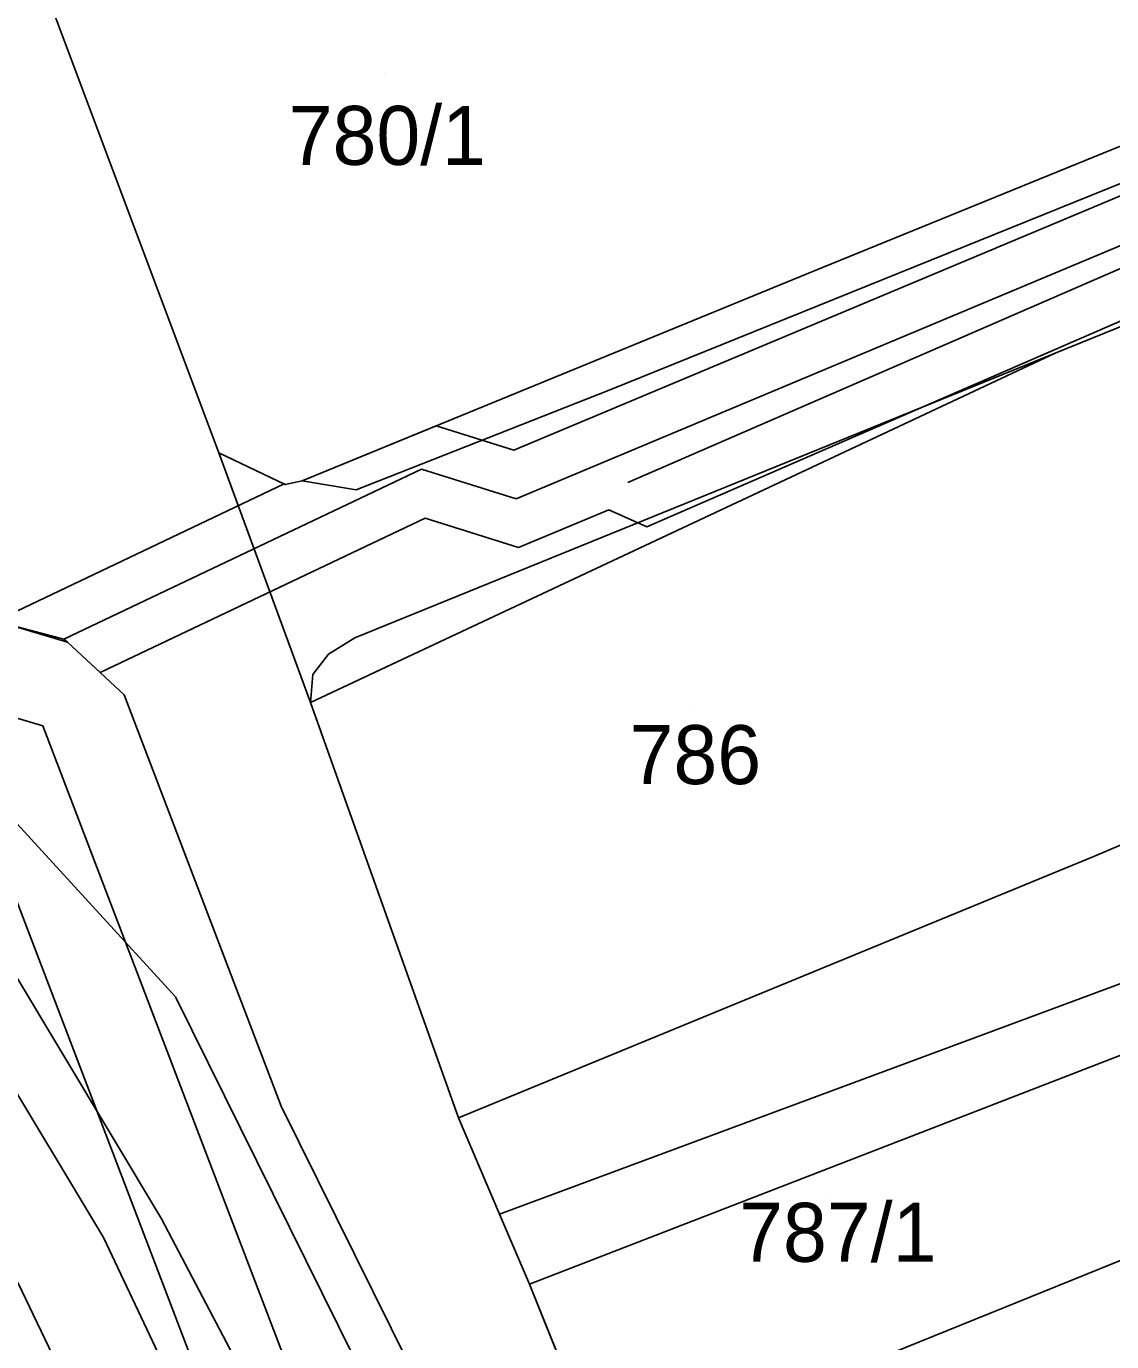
# Model space of a CAD drawing. Extents: x -263423 to -261326, y -1240067 to -1237864.
# Drawn here: x -262860.21 to -262823.4, y -1239293 to -1239248.39 of the extents above; entities that cross this region are included whole.
import ezdxf

# ---------------------------------------------------------------- set-up
doc = ezdxf.new("R2010")
doc.units = 0
for name, color, linetype in [('body_kn', 7, 'Continuous'), ('kladpar_druhypozemkov', 7, 'Continuous'), ('kladpar_hranice', 7, 'Continuous'), ('kladpar_parcelnecisla', 7, 'Continuous'), ('kladpar_plochy', 7, 'Continuous'), ('tarchy_linie', 7, 'Continuous'), ('zappar_hrandruhpozemk', 7, 'Continuous')]:
    doc.layers.add(name, color=color, linetype=linetype)

msp = doc.modelspace()

# ---------------------------------------------------------------- linework, layer by layer
at = {"layer": 'body_kn'}
for p, q in [((-262833.51, -1239256.69), (-262833.51, -1239256.69)), ((-262825.32, -1239259.48), (-262825.32, -1239259.48)), ((-262840.45, -1239260.73), (-262840.45, -1239260.73)), ((-262846.31, -1239261.94), (-262846.31, -1239261.94)), ((-262853.69, -1239262.86), (-262853.69, -1239262.86)), ((-262843.68, -1239262.77), (-262843.68, -1239262.77)), ((-262846.81, -1239263.41), (-262846.81, -1239263.41)), ((-262851.47, -1239263.91), (-262851.47, -1239263.91)), ((-262851.43, -1239263.93), (-262851.43, -1239263.93)), ((-262850.86, -1239263.81), (-262850.86, -1239263.81)), ((-262839.81, -1239263.86), (-262839.81, -1239263.86)), ((-262849.03, -1239264.11), (-262849.03, -1239264.11)), ((-262843.6, -1239264.42), (-262843.6, -1239264.42)), ((-262840.46, -1239264.79), (-262840.46, -1239264.79)), ((-262846.69, -1239265.07), (-262846.69, -1239265.07)), ((-262839.17, -1239265.37), (-262839.17, -1239265.37)), ((-262843.52, -1239266.07), (-262843.52, -1239266.07)), ((-262858.94, -1239269.17), (-262858.94, -1239269.17)), ((-262858.94, -1239269.17), (-262858.94, -1239269.17)), ((-262858.82, -1239269.28), (-262858.82, -1239269.28)), ((-262849.07, -1239269.13), (-262849.07, -1239269.13)), ((-262849.97, -1239269.68), (-262849.97, -1239269.68)), ((-262857.71, -1239270.3), (-262857.71, -1239270.3)), ((-262850.5, -1239270.37), (-262850.5, -1239270.37)), ((-262856.89, -1239271.06), (-262856.89, -1239271.06)), ((-262850.58, -1239271.32), (-262850.58, -1239271.32)), ((-262850.58, -1239271.32), (-262850.58, -1239271.32)), ((-262859.65, -1239272.11), (-262859.65, -1239272.11)), ((-262823.98, -1239276.53), (-262823.98, -1239276.53)), ((-262823.98, -1239276.53), (-262823.98, -1239276.53)), ((-262855.16, -1239281.3), (-262855.16, -1239281.3)), ((-262851.57, -1239285.01), (-262851.57, -1239285.01)), ((-262845.56, -1239285.41), (-262845.56, -1239285.41)), ((-262855.63, -1239288.83), (-262855.63, -1239288.83)), ((-262844.17, -1239288.68), (-262844.17, -1239288.68)), ((-262857.6, -1239289.47), (-262857.6, -1239289.47)), ((-262843.15, -1239291.05), (-262843.15, -1239291.05)), ((-262843.15, -1239291.05), (-262843.15, -1239291.05))]:
    msp.add_line(p, q, dxfattribs=at)
at = {"layer": 'kladpar_druhypozemkov'}
for p, q in [((-262848.07, -1239249.99), (-262848.07, -1239249.99)), ((-262837.67, -1239271.49), (-262837.67, -1239271.49)), ((-262833.07, -1239288.09), (-262833.07, -1239288.09))]:
    msp.add_line(p, q, dxfattribs=at)
at = {"layer": 'kladpar_hranice'}
for points in [[(-262876.94, -1239194.62), (-262873.93, -1239204.53), (-262869.83, -1239217.58), (-262867.69, -1239224.11), (-262867.04, -1239226.16), (-262865.44, -1239231.28), (-262860.88, -1239243.51), (-262859.93, -1239246.2), (-262853.69, -1239262.86), (-262850.58, -1239271.32), (-262845.56, -1239285.41), (-262844.17, -1239288.68), (-262843.15, -1239291.05), (-262840.62, -1239297.33)], [(-262801.24, -1239243.54), (-262833.51, -1239256.69), (-262850.86, -1239263.81), (-262851.43, -1239263.93), (-262853.69, -1239262.86), (-262859.93, -1239246.2), (-262860.88, -1239243.51), (-262865.44, -1239231.28), (-262838.39, -1239221.89), (-262811.78, -1239209.44)], [(-262801.24, -1239243.54), (-262781.39, -1239235.39), (-262754.82, -1239224.92), (-262754.34, -1239223.21), (-262753.82, -1239222.65), (-262752.93, -1239225.34), (-262751.64, -1239230.32), (-262766.74, -1239235.9), (-262771.22, -1239237.71), (-262775.96, -1239239.64), (-262785.18, -1239243.38), (-262805.66, -1239251.51), (-262825.32, -1239259.48), (-262850.58, -1239271.32), (-262853.69, -1239262.86), (-262851.43, -1239263.93), (-262850.86, -1239263.81), (-262833.51, -1239256.69), (-262801.24, -1239243.54)], [(-262805.66, -1239251.51), (-262803.75, -1239256.77), (-262803.39, -1239257.92), (-262801.95, -1239261.7), (-262800.22, -1239266.44), (-262823.98, -1239276.53), (-262845.56, -1239285.41), (-262850.58, -1239271.32), (-262825.32, -1239259.48), (-262805.66, -1239251.51)], [(-262823.98, -1239276.53), (-262800.22, -1239266.44), (-262794.84, -1239264.08), (-262792.97, -1239268.69), (-262796.94, -1239270.32), (-262822.48, -1239280.63), (-262821.58, -1239282.69), (-262819.17, -1239288.65), (-262840.62, -1239297.33), (-262843.15, -1239291.05), (-262844.17, -1239288.68), (-262845.56, -1239285.41), (-262823.98, -1239276.53)], [(-262793.62, -1239277.89), (-262788.75, -1239275.84), (-262785.54, -1239274.49), (-262783.04, -1239280.5), (-262787.13, -1239282.2), (-262786.51, -1239283.89), (-262785.37, -1239286.59), (-262785.19, -1239287.1), (-262787.22, -1239287.18), (-262790.65, -1239287.43), (-262790.83, -1239286.91), (-262793.88, -1239287.04), (-262799.31, -1239288.83), (-262813.6, -1239295.06), (-262837.24, -1239305.09), (-262840.62, -1239297.33), (-262819.17, -1239288.65), (-262793.62, -1239277.89)]]:
    msp.add_lwpolyline(points, dxfattribs=at)
at = {"layer": 'kladpar_plochy'}
for p, q in [((-262859.93, -1239246.2), (-262853.69, -1239262.86)), ((-262853.69, -1239262.86), (-262850.58, -1239271.32)), ((-262850.58, -1239271.32), (-262845.56, -1239285.41)), ((-262845.56, -1239285.41), (-262844.17, -1239288.68)), ((-262844.17, -1239288.68), (-262843.15, -1239291.05)), ((-262843.15, -1239291.05), (-262840.62, -1239297.33))]:
    msp.add_line(p, q, dxfattribs=at)
msp.add_lwpolyline([(-262801.24, -1239243.54), (-262833.51, -1239256.69), (-262850.86, -1239263.81), (-262851.43, -1239263.93), (-262853.69, -1239262.86), (-262859.93, -1239246.2), (-262860.88, -1239243.51), (-262865.44, -1239231.28), (-262838.39, -1239221.89), (-262811.78, -1239209.44)], dxfattribs=at)
for points in [[(-262801.24, -1239243.54), (-262781.39, -1239235.39), (-262754.82, -1239224.92), (-262754.34, -1239223.21), (-262753.82, -1239222.65), (-262752.93, -1239225.34), (-262751.64, -1239230.32), (-262766.74, -1239235.9), (-262771.22, -1239237.71), (-262775.96, -1239239.64), (-262785.18, -1239243.38), (-262805.66, -1239251.51), (-262825.32, -1239259.48), (-262850.58, -1239271.32), (-262853.69, -1239262.86), (-262851.43, -1239263.93), (-262850.86, -1239263.81), (-262833.51, -1239256.69)], [(-262805.66, -1239251.51), (-262803.75, -1239256.77), (-262803.39, -1239257.92), (-262801.95, -1239261.7), (-262800.22, -1239266.44), (-262823.98, -1239276.53), (-262845.56, -1239285.41), (-262850.58, -1239271.32), (-262825.32, -1239259.48)], [(-262823.98, -1239276.53), (-262800.22, -1239266.44), (-262794.84, -1239264.08), (-262792.97, -1239268.69), (-262796.94, -1239270.32), (-262822.48, -1239280.63), (-262821.58, -1239282.69), (-262819.17, -1239288.65), (-262840.62, -1239297.33), (-262843.15, -1239291.05), (-262844.17, -1239288.68), (-262845.56, -1239285.41)], [(-262793.62, -1239277.89), (-262788.75, -1239275.84), (-262785.54, -1239274.49), (-262783.04, -1239280.5), (-262787.13, -1239282.2), (-262786.51, -1239283.89), (-262785.37, -1239286.59), (-262785.19, -1239287.1), (-262787.22, -1239287.18), (-262790.65, -1239287.43), (-262790.83, -1239286.91), (-262793.88, -1239287.04), (-262799.31, -1239288.83), (-262813.6, -1239295.06), (-262837.24, -1239305.09), (-262840.62, -1239297.33), (-262819.17, -1239288.65)]]:
    msp.add_lwpolyline(points, close=True, dxfattribs=at)
at = {"layer": 'tarchy_linie'}
for points in [[(-262919.47, -1239083.19), (-262910.4, -1239113.29), (-262903.08, -1239136.85), (-262892.92, -1239170.2), (-262878.03, -1239218.5), (-262872.8, -1239236.18), (-262865.97, -1239259.6), (-262862.37, -1239270.8), (-262860.78, -1239275.15), (-262855.16, -1239281.3), (-262847.42, -1239296.93), (-262841.21, -1239314.37), (-262837.3, -1239325.72), (-262833.82, -1239334.62), (-262823.57, -1239363.35), (-262812.24, -1239393.87)], [(-262858.94, -1239269.17), (-262846.81, -1239263.41), (-262843.6, -1239264.42), (-262802.05, -1239246.99), (-262755.57, -1239228.56), (-262754.93, -1239226.6), (-262753.47, -1239225.49), (-262748.33, -1239223.7)], [(-262839.81, -1239263.86), (-262816.46, -1239253.72), (-262776.84, -1239237.35), (-262747.13, -1239227.57)], [(-262868.71, -1239244.57), (-262864.46, -1239259.14), (-262861.45, -1239268.5), (-262858.82, -1239269.28), (-262856.89, -1239271.06), (-262851.57, -1239285.01), (-262845.97, -1239296.31)], [(-262815.82, -1239255.23), (-262839.17, -1239265.37), (-262840.46, -1239264.79), (-262843.52, -1239266.07), (-262846.69, -1239265.07), (-262857.71, -1239270.3), (-262858.82, -1239269.28), (-262858.94, -1239269.17), (-262861.26, -1239268.56), (-262851.47, -1239263.91), (-262851.43, -1239263.93), (-262850.86, -1239263.81), (-262846.31, -1239261.94), (-262843.68, -1239262.77), (-262802.64, -1239245.55)], [(-262876.1, -1239267.26), (-262859.65, -1239272.11), (-262836.46, -1239332.83), (-262813.8, -1239395.79), (-262782.96, -1239480.21), (-262751.68, -1239564.86), (-262738.56, -1239596.25), (-262720.83, -1239681.08), (-262703.16, -1239765.24), (-262676.39, -1239868.22), (-262673.88, -1239876.15)], [(-262887.4, -1239271.82), (-262886.03, -1239271.48), (-262870.18, -1239272.08), (-262862.78, -1239274.26), (-262862.15, -1239275.98), (-262860.74, -1239277.53), (-262839.23, -1239333.86), (-262816.57, -1239396.8)]]:
    msp.add_lwpolyline(points, dxfattribs=at)
at = {"layer": 'zappar_hrandruhpozemk'}
for p, q in [((-262849.07, -1239269.13), (-262825.32, -1239259.48)), ((-262866.07, -1239275.36), (-262857.6, -1239289.47)), ((-262822.48, -1239280.63), (-262844.17, -1239288.68)), ((-262843.15, -1239291.05), (-262821.58, -1239282.69)), ((-262857.6, -1239289.47), (-262849.85, -1239305.78))]:
    msp.add_line(p, q, dxfattribs=at)
for points in [[(-262816.44, -1239251.03), (-262840.45, -1239260.73), (-262849.03, -1239264.11), (-262850.86, -1239263.81)], [(-262850.58, -1239271.32), (-262850.5, -1239270.37), (-262849.97, -1239269.68), (-262849.07, -1239269.13)], [(-262863.97, -1239274.93), (-262855.63, -1239288.83), (-262852.38, -1239295.01), (-262847.93, -1239305.11)], [(-262860.5, -1239290.99), (-262853.02, -1239306.6), (-262846.33, -1239325.05)]]:
    msp.add_lwpolyline(points, dxfattribs=at)

# ---------------------------------------------------------------- texts
at = {"layer": 'kladpar_parcelnecisla'}
for s, p in [('780/1', (-262851.315, -1239253.09)), ('786', (-262839.753, -1239274.09)), ('787/1', (-262836.037, -1239290.29))]:
    msp.add_text(s, height=2, dxfattribs=at).set_placement(p)

doc.saveas('drawing.dxf')
